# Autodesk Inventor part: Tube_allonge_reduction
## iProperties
Shininess: 64.0
Length Units: 11269
Angle Units: 11279
Time Units: 11290
Mass Units: 11283
Length Display Precision: 3
Angle Display Precision: 2
Compacted: True
Part Number: Tube_allonge_reduction
Document SubType Name: Modeling
Created: 2008-04
Material: Par défaut
Designer: plup
Density: 1 g/cm^3
Density: 0.0
Volumn: 0.0
Area: 0.0
PropertySet Name: Model Information
Control State: 0
Master: False
Checked Out: False
MATIERE_PIECE: X2CrNi 18-11
OBSERVATIONS: Tube Ø..
DESIGNATION: Manchon
Author: plup
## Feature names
1. Extrusion1
